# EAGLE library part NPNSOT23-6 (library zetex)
NPN TRANSISTOR
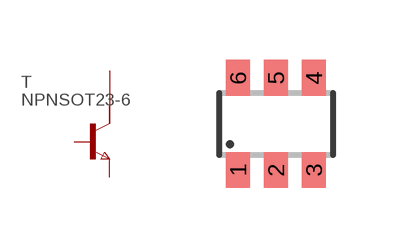
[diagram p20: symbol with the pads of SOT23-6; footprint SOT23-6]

Designator prefix T

## NPNSOT23-6 (MPN: ZXT13N50DE6; OC_FARNELL: 9525394; OC_NEWARK: 98K4165)  [SOT23-6]
1  C1  pas
2  C2  pas
3  B  pas
4  E  pas
5  C3  pas
6  C4  pas

## Footprint SOT23-6 (pad centres in mm)
Small Outline Transistor 6 lead
smd 0.6 x 0.9: 1 -0.95,-1.15; 2 0,-1.15; 3 0.95,-1.15; 4 0.95,1.15; 5 0,1.15; 6 -0.95,1.15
